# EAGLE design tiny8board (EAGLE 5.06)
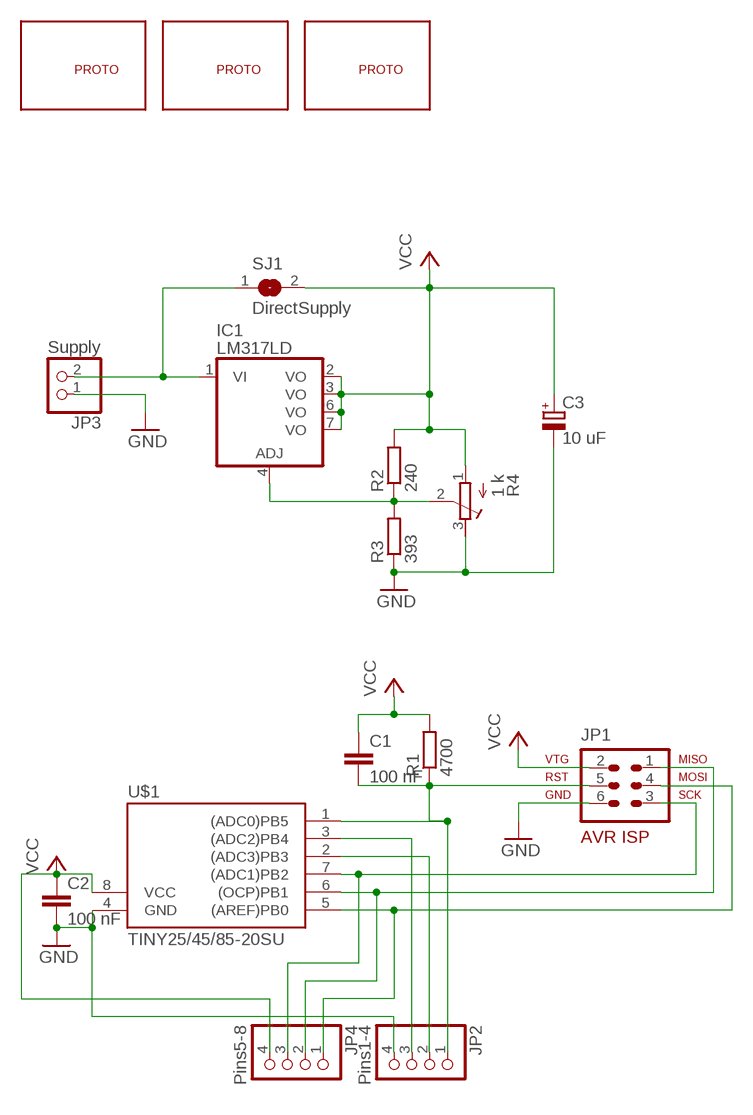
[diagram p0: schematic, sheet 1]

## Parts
C1  100 nF  C-EUC0805  [C0805]
C2  100 nF  C-EUC0805  [C0805]
C3  10 uF  CPOL-EU153CLV-0405  [153CLV-0405]
IC1  LM317LD  [SO08]
JP1  AVR-ISP-6  [AVR-ISP-6]
JP2  Pins1-4  PINHD-1X4  [1X04]
JP3  Supply  PINHD-1X2  [1X02]
JP4  Pins5-8  PINHD-1X4  [1X04]
R1  4700  R-EU_R0805  [R0805]
R2  240  R-EU_R0805  [R0805]
R3  393  R-EU_R0805  [R0805]
R4  1 k  R-TRIMM3165W  [RTRIM3165W]
SJ1  DirectSupply  SJ  [SJ]
U$1  TINY25/45/85-20SU  [SOIC8]
U$2  PROTO-AREA  [PROTO-AREA]
U$3  PROTO-AREA  [PROTO-AREA]  (not placed on a sheet)
U$4  PROTO-AREA  [PROTO-AREA]
U$5  PROTO-AREA  [PROTO-AREA]

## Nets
GND: C2.2 C3.- JP1.6 JP2.4 JP3.1 R3.1 R4.3(A) U$1.4(GND)
N$1: C1.2 JP1.5 JP2.1 R1.1 U$1.1((ADC0)PB5)
N$2: IC1.1(VI) JP3.2 SJ1.1
N$3: JP1.4 JP4.1 U$1.5((AREF)PB0)
N$4: JP1.1 JP4.2 U$1.6((OCP)PB1)
N$5: JP1.3 JP4.3 U$1.7((ADC1)PB2)
N$6: JP2.2 U$1.2((ADC3)PB3)
N$7: IC1.4(ADJ) R2.1 R3.2 R4.2(S)
N$8: JP2.3 U$1.3((ADC2)PB4)
VCC: C1.1 C2.1 C3.+ IC1.2(VO) IC1.3(VO) IC1.6(VO) IC1.7(VO) JP1.2 JP4.4 R1.2 R2.2 R4.1(E) SJ1.2 U$1.8(VCC)

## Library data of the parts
C1 C2 = rcl:C-EU: CAPACITOR, European symbol
C3 = rcl:CPOL-EU: POLARIZED CAPACITOR, European symbol
IC1 = linear:LM317LD: LOW CURRENT 1.2 TO 37V ADJUSTABLE VOLTAGE REGULATOR Source: http://pdf.alldatasheet.com
JP1 = avr-6:AVR-ISP-6: AVR ISP-6 Serial Programming Header
JP2 JP4 = pinhead:PINHD-1X4: PIN HEADER
JP3 = pinhead:PINHD-1X2: PIN HEADER
R1-R3 = rcl:R-EU_: RESISTOR, European symbol
R4 = rcl:R-TRIMM: Trimm resistor
SJ1 = jumper:SJ: SMD solder JUMPER
U$1 = avr-6:TINY25/45/85
U$2-U$5 = proto:PROTO-AREA

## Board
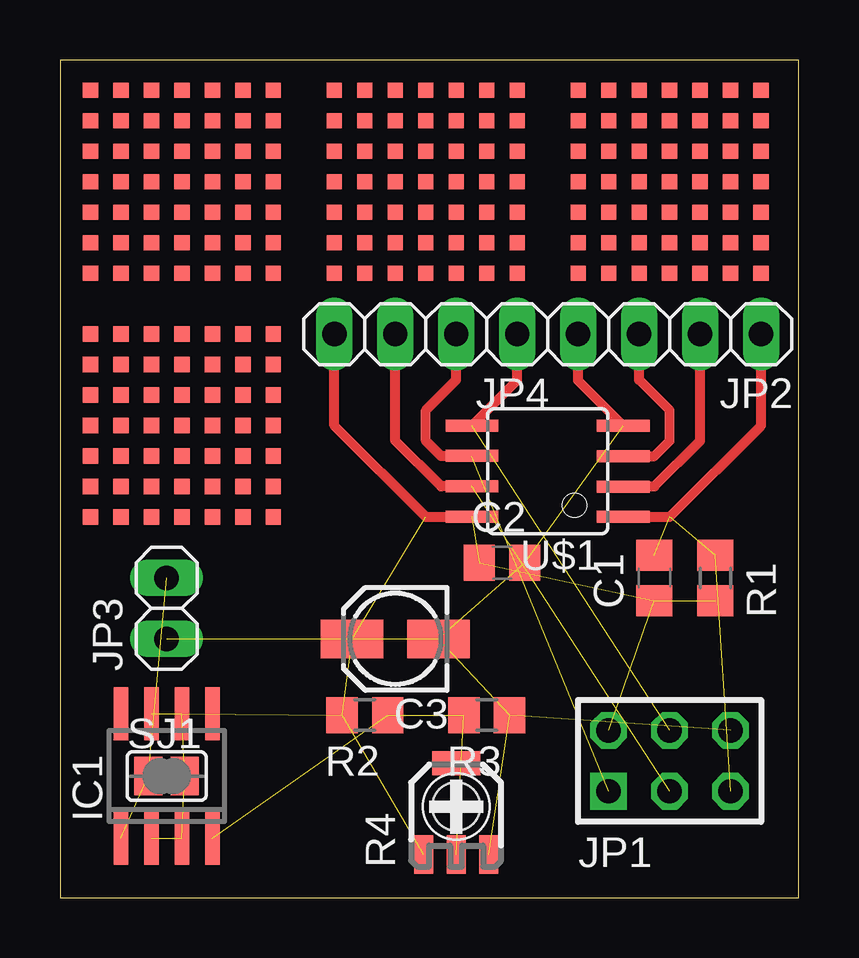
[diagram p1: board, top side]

Size 30.79 x 34.91 mm. Coordinates in mm from the lower left corner, seen from the top.
Outline: 0,0 30.79,0 30.79,34.91 0,34.91 0,0
Copper layers (1*16): Top 0.035mm / dielectric 1.5mm / Bottom 0.035mm
Design rules "default": minimum track width 10mil, minimum drill 24mil, track to track 8mil, track to pad 8mil, pad to pad 8mil, via to via 8mil, smd to smd 8mil, copper to edge 40mil, drill to drill 8mil, minimum pad ring 10mil, minimum via ring 8mil, stop-mask expansion 4mil, vias tented up to drill 0mil, thermal gap 10mil

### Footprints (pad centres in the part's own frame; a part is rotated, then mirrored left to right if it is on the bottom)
C0805 = smd 1.3 x 1.5: 1 -0.95,0; 2 0.95,0
153CLV-0405 = smd 2.6 x 1.6: + 1.8,0; - -1.8,0
SO08 = smd 0.6 x 2.2: 1 -1.905,-2.6; 2 -0.635,-2.6; 3 0.635,-2.6; 4 1.905,-2.6; 5 1.905,2.6; 6 0.635,2.6; 7 -0.635,2.6; 8 -1.905,2.6
AVR-ISP-6 = drill 1.016 square: 1 -2.54,-1.27 | drill 1.016 octagon: 2 -2.54,1.27; 3 0,-1.27; 4 0,1.27; 5 2.54,-1.27; 6 2.54,1.27
1X04 = drill 1.016 long: 1 -3.81,0; 2 -1.27,0; 3 1.27,0; 4 3.81,0
1X02 = drill 1.016 long: 1 -1.27,0; 2 1.27,0
R0805 = smd 1.3 x 1.5: 1 -0.95,0; 2 0.95,0
RTRIM3165W = smd 0.8 x 1.6: 1 -1.35,-2; 2 0,-2; 3 1.35,-2 | smd 2 x 1: 4 0,1.8 | hole 2: 0,0
SJ = smd 1.168 x 1.6: 1 -0.762,0; 2 0.762,0
SOIC8 = smd 0.5 x 2.2: 1 -1.905,-3.154; 2 -0.645,-3.154; 3 0.625,-3.154; 4 1.895,-3.154; 5 1.905,3.154; 6 0.635,3.154; 7 -0.635,3.154; 8 -1.905,3.154
PROTO-AREA = smd 0.635 x 0.635: P$2 -3.81,3.81; P$3 -2.54,3.81; P$4 -2.54,2.54; P$5 -3.81,2.54; P$6 -1.27,3.81; P$7 -1.27,2.54; P$8 0,2.54; P$9 0,3.81; P$10 1.27,3.81; P$11 1.27,2.54; P$12 2.54,2.54; P$13 2.54,3.81; P$14 -3.81,1.27; P$15 -2.54,1.27; P$16 -1.27,1.27; P$17 0,1.27; P$18 1.27,1.27; P$19 2.54,1.27; P$20 2.54,0; P$21 1.27,0; P$22 0,0; P$23 -1.27,0; P$24 -2.54,0; P$25 -3.81,0; P$26 -3.81,-1.27; P$27 -2.54,-1.27; P$28 -1.27,-1.27; P$29 0,-1.27; P$30 1.27,-1.27; P$31 2.54,-1.27; P$32 2.54,-2.54; P$33 1.27,-2.54; P$34 0,-2.54; P$35 -1.27,-2.54; P$36 -2.54,-2.54; P$37 -3.81,-2.54; P$38 -3.81,-3.81; P$39 -2.54,-3.81; P$40 -1.27,-3.81; P$41 0,-3.81; P$42 1.27,-3.81; P$43 2.54,-3.81; P$44 3.81,-3.81; P$45 3.81,-2.54; P$46 3.81,-1.27; P$47 3.81,0; P$48 3.81,1.27; P$49 3.81,2.54; P$50 3.81,3.81

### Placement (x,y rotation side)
C1  24.77,13.34 90 top
C2  18.41,13.97 0 top
C3  13.97,10.79 180 top
IC1  4.45,5.08 0 top
JP1  25.4,5.71 0 top
JP2  25.4,23.5 180 top
JP3  4.45,12.06 90 top
JP4  15.24,23.5 180 top
R1  27.3,13.34 270 top
R2  12.7,7.62 180 top
R3  17.78,7.62 180 top
R4  16.51,3.81 0 top
SJ1  4.45,5.08 0 top
U$1  20.32,17.78 90 top
U$2  15.24,29.84 0 top
U$3  25.4,29.84 0 top
U$4  5.08,29.84 0 top
U$5  5.08,19.68 0 top

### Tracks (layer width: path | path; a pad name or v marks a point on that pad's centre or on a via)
GND  (6 unrouted)
  Top 0.406: U$1.4 21.59,21.56 JP2.4
N$1  (3 unrouted)
  Top 0.406: JP2.1 29.21,19.68 25.4,15.88 U$1.1
N$2  (2 unrouted)
N$3  (1 unrouted)
  Top 0.406: U$1.5 19.05,21.57 JP4.1
N$4  (1 unrouted)
  Top 0.406: JP4.2 16.51,21.59 15.24,20.32 15.24,19.05 15.88,18.41 U$1.6
N$5  (1 unrouted)
  Top 0.406: JP4.3 13.97,19.05 15.88,17.14 U$1.7
N$6
  Top 0.406: JP2.2 26.67,19.05 24.77,17.14 23.48,17.14 U$1.2
N$7  (3 unrouted)
N$8
  Top 0.406: JP2.3 24.13,21.59 25.4,20.32 25.4,19.05 24.77,18.41 23.48,18.41 U$1.3
VCC  (12 unrouted)
  Top 0.406: JP4.4 11.43,19.68 15.24,15.88 U$1.8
